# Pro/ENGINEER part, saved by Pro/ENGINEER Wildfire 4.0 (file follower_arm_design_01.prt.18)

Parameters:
  METRIC = "NO"

Other parameters: PITCH, DRILL_DIAMETER, THREAD_DIAMETER, THREADS_PER_INCH, THREAD_DEPTH, THREAD_LENGTH, DRILL_POINT_ANGLE, DRILL_DEPTH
